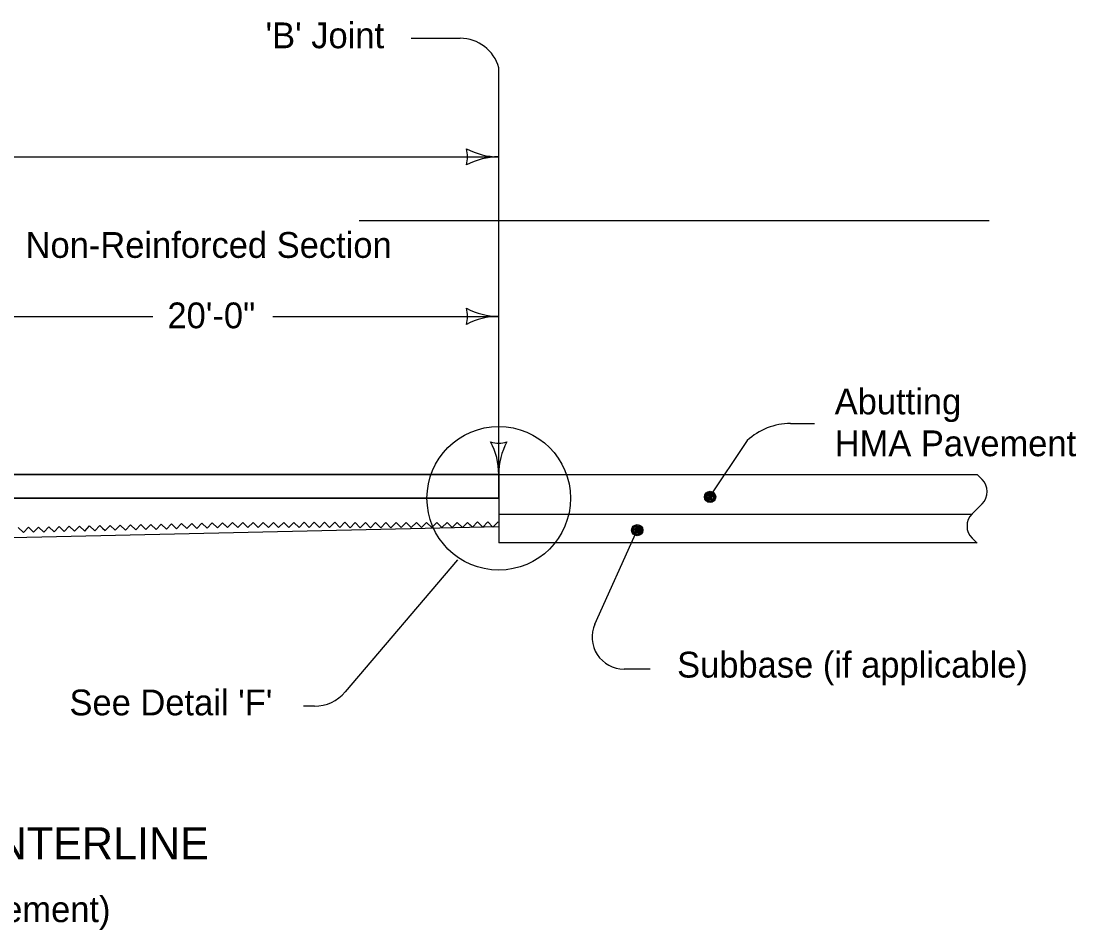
# Model space of a CAD drawing. Extents: x 5546 to 81668, y 3174 to 15999.
# Drawn here: x 15062 to 15716, y 6998 to 7562 of the extents above; entities that cross this region are included whole.
import ezdxf

# ---------------------------------------------------------------- set-up
doc = ezdxf.new("R2010")
doc.units = 0
for name, color, linetype in [('PS_BOLT', 7, 'Continuous'), ('PS_CONST', 7, 'Continuous'), ('PS_DAWA', 7, 'Continuous'), ('PS_DIM', 7, 'Continuous'), ('PS_SHAPE', 7, 'Continuous')]:
    doc.layers.add(name, color=color, linetype=linetype)

msp = doc.modelspace()

# ---------------------------------------------------------------- linework, layer by layer
at = {"layer": 'PS_CONST'}
for p, q in [((15303.91, 7550.97), (15334.35, 7550.97)), ((15358.25, 7280.38), (15358.25, 7532.64)), ((14196.98, 7477.41), (15358.25, 7477.41)), ((15539.37, 7311.93), (15554.17, 7311.93)), ((15512.36, 7301.3), (15488.64, 7265.76)), ((15417.92, 7187.46), (15444.17, 7245.75)), ((15332.74, 7227.36), (15262.96, 7145.35)), ((15452.2, 7159.53), (15435.98, 7159.53)), ((15243.92, 7136.55), (15237.18, 7136.55))]:
    msp.add_line(p, q, dxfattribs=at)
for points in [[(15489.12, 7263.25), (15490.28, 7263.78), (15492.11, 7264.34), (15492.46, 7266.19), (15492.21, 7267.81), (15491.04, 7269.3), (15489.31, 7269.15), (15487.49, 7268.89), (15486.61, 7267.44), (15486.45, 7265.91), (15487.53, 7263.9), (15488.86, 7263.73), (15490.68, 7264.2), (15492.18, 7265.36), (15492.13, 7267.09), (15490.97, 7268.48), (15489.33, 7268.64), (15487.5, 7268.28), (15487.23, 7267.25), (15486.86, 7266.02), (15487.72, 7264.51), (15489.04, 7264.55), (15490.56, 7264.8), (15491.66, 7265.65), (15491.1, 7267.16), (15489.96, 7268.05), (15488.43, 7268.1), (15488.04, 7267.28), (15487.56, 7266.35), (15488.31, 7265.15), (15489.44, 7264.87), (15490.44, 7265.41), (15490.51, 7266.53), (15489.98, 7267.33), (15488.95, 7267.61), (15488.46, 7267.19), (15488.17, 7266.57), (15488.7, 7265.67), (15489.42, 7265.48), (15490.12, 7265.91), (15490, 7266.52), (15489.48, 7266.91), (15488.77, 7266.89), (15488.78, 7266.38), (15489.41, 7266.1)], [(15444.44, 7242.58), (15443.27, 7243.1), (15441.45, 7243.66), (15441.09, 7245.51), (15441.35, 7247.13), (15442.51, 7248.63), (15444.24, 7248.48), (15446.07, 7248.22), (15446.94, 7246.77), (15447.1, 7245.23), (15446.02, 7243.23), (15444.69, 7243.06), (15442.87, 7243.52), (15441.38, 7244.68), (15441.43, 7246.42), (15442.59, 7247.81), (15444.22, 7247.96), (15446.05, 7247.61), (15446.32, 7246.58), (15446.69, 7245.35), (15445.84, 7243.84), (15444.51, 7243.88), (15442.99, 7244.13), (15441.89, 7244.98), (15442.45, 7246.49), (15443.6, 7247.37), (15445.12, 7247.43), (15445.51, 7246.6), (15445.99, 7245.67), (15445.24, 7244.47), (15444.11, 7244.2), (15443.11, 7244.74), (15443.04, 7245.86), (15443.57, 7246.66), (15444.6, 7246.94), (15445.1, 7246.51), (15445.39, 7245.89), (15444.85, 7244.99), (15444.13, 7244.81), (15443.43, 7245.24), (15443.55, 7245.85), (15444.07, 7246.24), (15444.78, 7246.22), (15444.77, 7245.7), (15444.15, 7245.42)]]:
    msp.add_lwpolyline(points, dxfattribs=at)
for centre, radius in [((15358.25, 7265.53), 44.55), ((15489.39, 7266.43), 3.47), ((15444.17, 7245.75), 3.47)]:
    msp.add_circle(centre, radius, dxfattribs=at)
for centre, radius, start, end in [((15334.35, 7526.22), 24.75, 15.02992, 90), ((15539.37, 7272.33), 39.6, 90, 132.998), ((15358.25, 7316.22), 16.51, 252.26665, 287.73335), ((15315.5, 7280.38), 42.75, 360, 28.07249), ((15401, 7280.38), 42.75, 151.92751, 180), ((15435.97, 7179.33), 19.8, 155.76197, 270)]:
    msp.add_arc(centre, radius, start, end, dxfattribs=at)
at = {"layer": 'PS_DAWA'}
for p, q in [((15001.85, 7378.41), (15143.68, 7378.41)), ((15217.97, 7378.41), (15358.25, 7378.41))]:
    msp.add_line(p, q, dxfattribs=at)
for centre, radius, start, end in [((15322.41, 7477.41), 16.51, 342.26665, 17.73335), ((15358.25, 7520.16), 42.75, 241.92751, 270), ((15358.25, 7434.66), 42.75, 90, 118.07249), ((15322.41, 7378.41), 16.51, 342.26665, 17.73335), ((15358.25, 7421.16), 42.75, 241.92751, 270), ((15358.25, 7335.66), 42.75, 90, 118.07249)]:
    msp.add_arc(centre, radius, start, end, dxfattribs=at)
at = {"layer": 'PS_DIM'}
for p, q in [((15271.54, 7437.97), (15662.44, 7437.97)), ((15358.25, 7280.38), (15001.85, 7280.38)), ((15358.25, 7265.53), (15358.25, 7280.38)), ((15658.18, 7277.25), (15655.05, 7280.38)), ((15001.85, 7265.53), (15358.25, 7265.53)), ((15651.92, 7255.87), (15658.18, 7262.13)), ((15655.05, 7237.61), (15651.92, 7240.75))]:
    msp.add_line(p, q, dxfattribs=at)
for centre, radius, start, end in [((15650.62, 7269.69), 10.69, 315, 45), ((15659.48, 7248.3), 10.69, 135, 225), ((15243.92, 7161.55), 25, 270, 319.6052)]:
    msp.add_arc(centre, radius, start, end, dxfattribs=at)
at = {"layer": 'PS_SHAPE'}
for p, q in [((14199.95, 7280.38), (15358.25, 7280.38)), ((15358.25, 7280.38), (15655.05, 7280.38)), ((15358.25, 7280.38), (15358.25, 7265.53)), ((15640.45, 7280.38), (15640.45, 7280.38)), ((15358.25, 7265.53), (14199.95, 7265.53)), ((15358.25, 7265.53), (15358.25, 7237.81)), ((15358.25, 7255.63), (15651.69, 7255.63)), ((15358.25, 7247.88), (14233.59, 7222.47)), ((15654.85, 7237.81), (15358.25, 7237.81))]:
    msp.add_line(p, q, dxfattribs=at)
for points in [[(15060.07, 7247.41), (15063.31, 7244.32), (15066.41, 7247.56), (15069.65, 7244.47), (15072.74, 7247.71), (15075.98, 7244.61), (15079.07, 7247.86), (15082.32, 7244.76), (15085.41, 7248), (15088.65, 7244.91), (15091.74, 7248.15), (15094.99, 7245.06), (15098.08, 7248.3), (15101.32, 7245.21), (15104.41, 7248.45), (15107.65, 7245.36), (15110.75, 7248.6), (15112.37, 7247.05)], [(15112.37, 7247.06), (15113.99, 7245.51), (15117.08, 7248.75), (15120.32, 7245.66), (15123.41, 7248.9), (15126.65, 7245.81), (15129.75, 7249.05), (15132.99, 7245.95), (15136.09, 7249.2), (15139.33, 7246.1), (15142.41, 7249.34), (15145.66, 7246.25), (15148.75, 7249.49), (15151.99, 7246.4), (15155.09, 7249.64), (15158.33, 7246.55), (15161.42, 7249.79), (15164.66, 7246.69), (15167.75, 7249.94), (15171, 7246.85), (15174.09, 7250.09), (15177.33, 7247), (15180.42, 7250.24), (15183.66, 7247.14), (15186.76, 7250.39), (15188.38, 7248.84)], [(15188.37, 7248.98), (15189.95, 7247.4), (15193.12, 7250.57), (15196.29, 7247.4), (15199.45, 7250.58), (15202.63, 7247.41), (15205.79, 7250.58), (15208.96, 7247.42), (15212.13, 7250.59), (15215.3, 7247.43), (15218.46, 7250.6), (15221.63, 7247.44), (15224.8, 7250.61), (15227.97, 7247.45), (15231.13, 7250.61), (15234.31, 7247.45), (15237.47, 7250.62), (15240.64, 7247.46), (15243.81, 7250.63), (15246.98, 7247.47), (15250.14, 7250.64), (15253.31, 7247.48), (15256.48, 7250.65), (15259.65, 7247.49), (15262.81, 7250.65), (15264.4, 7249.07)], [(15264.4, 7248.85), (15265.99, 7247.27), (15269.15, 7250.43), (15272.32, 7247.27), (15275.49, 7250.44), (15278.66, 7247.28), (15281.82, 7250.45), (15284.99, 7247.29), (15288.16, 7250.46), (15291.33, 7247.3), (15294.49, 7250.47), (15297.67, 7247.31), (15300.83, 7250.48), (15304, 7247.31), (15307.17, 7250.48), (15310.34, 7247.32), (15313.5, 7250.49), (15316.67, 7247.33), (15319.84, 7250.5), (15323.01, 7247.34), (15326.17, 7250.51), (15329.35, 7247.34), (15332.51, 7250.52), (15335.68, 7247.35), (15338.85, 7250.53), (15340.43, 7248.94)], [(15340.4, 7249.29), (15341.98, 7247.7), (15345.15, 7250.88), (15348.32, 7247.71), (15351.49, 7250.88), (15354.65, 7247.71), (15357.82, 7250.88), (15358.28, 7250.42)]]:
    msp.add_lwpolyline(points, dxfattribs=at)

# ---------------------------------------------------------------- texts
at = {"layer": 'PS_BOLT'}
msp.add_text('SECTION THRU CENTERLINE', height=20, dxfattribs=at).set_placement((14800.95, 7041.44))
at = {"layer": 'PS_CONST'}
for s, p in [("'B' Joint", (15213.53, 7544.79)), ('Abutting', (15566.69, 7317.62)), ('HMA Pavement', (15566.69, 7291.62)), ('Subbase (if applicable)', (15468.91, 7154.3)), ("See Detail 'F'", (15091.89, 7130.85))]:
    msp.add_text(s, height=16, dxfattribs=at).set_placement(p)
at = {"layer": 'PS_DAWA'}
for s, p in [('Non-Reinforced Section', (15064.67, 7414.72)), ('20\'-0"', (15152.67, 7371.03))]:
    msp.add_text(s, height=16, dxfattribs=at).set_placement(p)
at = {"layer": 'PS_SHAPE'}
msp.add_text('(Abutting HMA Pavement)', height=16, dxfattribs=at).set_placement((14868.82, 7002.54))

doc.saveas('drawing.dxf')
